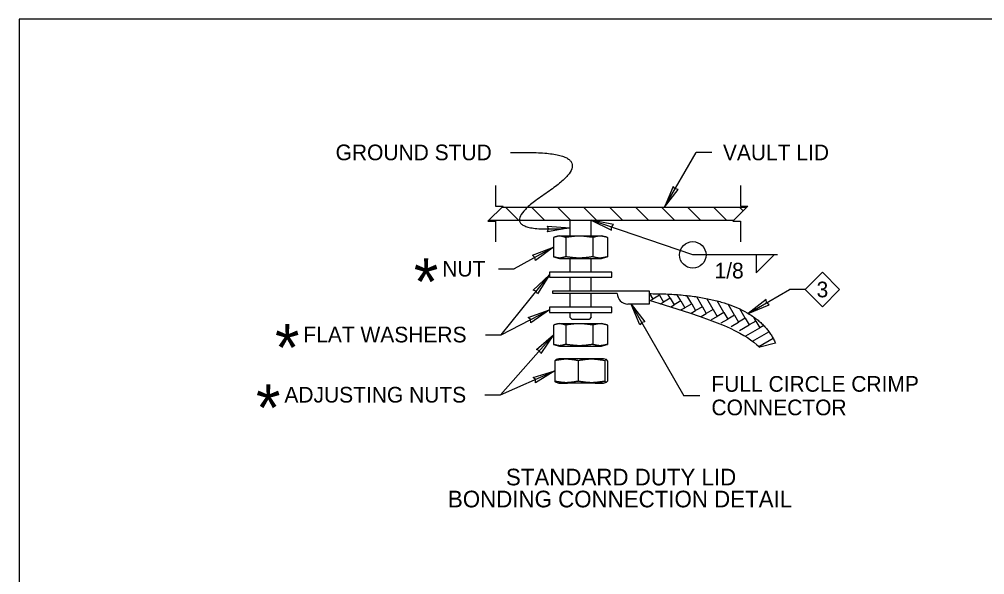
# Model space of a CAD drawing. Extents: x 99862 to 103151, y 100000 to 105076.
# Drawn here: x 99862 to 100847, y 104508 to 105076 of the extents above; entities that cross this region are included whole.
import ezdxf

# ---------------------------------------------------------------- set-up
doc = ezdxf.new("R2010")
doc.units = 0
for name, color, linetype in [('Level 1', 7, 'Continuous'), ('Level 10', 7, 'Continuous'), ('Level 11', 7, 'Continuous'), ('Level 13', 7, 'Continuous'), ('Level 15', 7, 'Continuous'), ('Level 20', 7, 'Continuous')]:
    doc.layers.add(name, color=color, linetype=linetype)

msp = doc.modelspace()

# ---------------------------------------------------------------- linework, layer by layer
at = {"layer": 'Level 1'}
for p, q in [((100354.24, 104883.61), (100604.11, 104883.61)), ((100358.14, 104883.61), (100371.32, 104870.43)), ((100384.66, 104883.61), (100397.84, 104870.43)), ((100411.17, 104883.61), (100424.35, 104870.43)), ((100437.69, 104883.61), (100450.87, 104870.43)), ((100464.21, 104883.61), (100477.39, 104870.43)), ((100490.72, 104883.61), (100503.9, 104870.43)), ((100517.24, 104883.61), (100530.42, 104870.43)), ((100543.76, 104883.61), (100556.93, 104870.43)), ((100570.27, 104883.61), (100583.45, 104870.43)), ((100596.79, 104883.61), (100600.45, 104879.95)), ((100341.06, 104870.43), (100590.93, 104870.43))]:
    msp.add_line(p, q, dxfattribs=at)
msp.add_lwpolyline([(99862, 102999.5), (103151, 102999.5), (103151, 105075.5), (99862, 105075.5)], close=True, dxfattribs=at)
at = {"layer": 'Level 10'}
for p, q in [((100423.63, 104870.43), (100423.63, 104854.53)), ((100445.5, 104854.53), (100445.5, 104870.43)), ((100413.14, 104854.53), (100407.73, 104853.02)), ((100413.14, 104854.53), (100455.99, 104854.53)), ((100461.4, 104853.02), (100455.99, 104854.53)), ((100407.75, 104853.03), (100406.97, 104852.8)), ((100406.97, 104852.8), (100406.97, 104833.11)), ((100419.42, 104852.8), (100419.42, 104833.11)), ((100447.01, 104852.8), (100447.01, 104833.11)), ((100461.38, 104853.03), (100462.16, 104852.8)), ((100462.16, 104852.8), (100462.16, 104833.11)), ((100406.97, 104833.09), (100413.14, 104831.38)), ((100413.14, 104831.38), (100455.99, 104831.38)), ((100423.63, 104831.38), (100423.63, 104817.43)), ((100445.5, 104817.43), (100445.5, 104831.38)), ((100455.99, 104831.38), (100461.4, 104832.88)), ((100461.38, 104832.88), (100462.16, 104833.11)), ((100423.63, 104812.16), (100423.63, 104798.34)), ((100445.5, 104798.34), (100445.5, 104812.16)), ((100423.63, 104795.71), (100423.63, 104781.57)), ((100445.5, 104781.57), (100445.5, 104795.71)), ((100423.63, 104776.3), (100423.63, 104771.38)), ((100445.5, 104771.38), (100445.5, 104776.3)), ((100425.88, 104769.13), (100423.63, 104771.38)), ((100443.25, 104769.13), (100425.88, 104769.13)), ((100445.5, 104771.38), (100443.25, 104769.13)), ((100407.75, 104763.57), (100406.97, 104763.34)), ((100406.97, 104763.34), (100406.97, 104743.65)), ((100413.14, 104765.07), (100407.73, 104763.57)), ((100413.14, 104765.07), (100455.99, 104765.07)), ((100419.42, 104763.34), (100419.42, 104743.65)), ((100447.01, 104763.34), (100447.01, 104743.65)), ((100461.4, 104763.57), (100455.99, 104765.07)), ((100461.38, 104763.57), (100462.16, 104763.34)), ((100462.16, 104763.34), (100462.16, 104743.65)), ((100406.97, 104743.64), (100413.14, 104741.92)), ((100413.14, 104741.92), (100455.99, 104741.92)), ((100455.99, 104741.92), (100461.4, 104743.43)), ((100461.38, 104743.42), (100462.16, 104743.65)), ((100408.37, 104727), (100409.6, 104728.06)), ((100408.37, 104727), (100408.37, 104706)), ((100412.41, 104728.85), (100409.56, 104728.05)), ((100432.27, 104727), (100432.27, 104706)), ((100460.97, 104728.06), (100458.12, 104728.85)), ((100459.17, 104727), (100459.17, 104706)), ((100462.16, 104727), (100460.93, 104728.07)), ((100462.16, 104727), (100462.16, 104706)), ((100408.37, 104706), (100409.6, 104704.93)), ((100409.56, 104704.94), (100412.41, 104704.15)), ((100458.12, 104704.15), (100460.97, 104704.95)), ((100462.16, 104706), (100460.93, 104704.94))]:
    msp.add_line(p, q, dxfattribs=at)
for centre, major_axis, start_param, end_param in [((100435.26, 104728.85), (22.85, 0), 0.625296, 3.141532), ((100435.26, 104728.85), (-14.06, 0), 0, 0.013106), ((100435.26, 104728.85), (22.85, 0), 0.00006, 0.625296), ((100435.27, 104704.15), (22.85, 0), 3.141653, 4.049582), ((100435.27, 104704.15), (22.85, 0), 0.625296, 3.141653), ((100435.27, 104704.15), (-14.06, 0), 0, 0.013106), ((100435.27, 104704.15), (-14.06, 0), 3.141593, 6.283185), ((100435.27, 104704.15), (22.85, 0), 5.37533, 6.283125), ((100435.27, 104704.15), (22.85, 0), 6.283125, 6.908482)]:
    msp.add_ellipse(centre, major_axis=major_axis, ratio=0.000017, start_param=start_param, end_param=end_param, dxfattribs=at)
for points in [[(100447.01, 104852.8), (100437.82, 104854.21), (100428.62, 104854.18), (100419.42, 104852.8)], [(100462.16, 104852.8), (100457.14, 104854.11), (100452.03, 104854.26), (100447.01, 104852.8)], [(100419.42, 104852.8), (100415.53, 104854.03), (100411.64, 104854.27), (100407.75, 104853.03)], [(100419.42, 104833.11), (100415.53, 104831.87), (100411.64, 104831.64), (100407.75, 104832.88)], [(100447.01, 104833.11), (100437.82, 104831.69), (100428.62, 104831.72), (100419.42, 104833.11)], [(100462.16, 104833.11), (100457.14, 104831.79), (100452.03, 104831.64), (100447.01, 104833.11)], [(100419.42, 104763.34), (100415.53, 104764.58), (100411.64, 104764.81), (100407.75, 104763.57)], [(100447.01, 104763.34), (100437.82, 104764.76), (100428.62, 104764.72), (100419.42, 104763.34)], [(100462.16, 104763.34), (100457.14, 104764.65), (100452.03, 104764.8), (100447.01, 104763.34)], [(100419.42, 104743.65), (100415.53, 104742.41), (100411.64, 104742.18), (100407.75, 104743.42)], [(100447.01, 104743.65), (100437.82, 104742.23), (100428.62, 104742.27), (100419.42, 104743.65)], [(100462.16, 104743.65), (100457.14, 104742.34), (100452.03, 104742.19), (100447.01, 104743.65)], [(100432.27, 104727), (100424.35, 104728.4), (100416.29, 104728.56), (100408.37, 104727)], [(100459.17, 104727), (100450.2, 104728.51), (100441.24, 104728.48), (100432.27, 104727)], [(100460.93, 104728.07), (100460.34, 104728.3), (100459.75, 104727.65), (100459.17, 104727)], [(100432.27, 104706), (100424.35, 104704.6), (100416.29, 104704.44), (100408.37, 104706)], [(100459.17, 104706), (100450.2, 104704.49), (100441.24, 104704.52), (100432.27, 104706)], [(100460.93, 104704.94), (100460.34, 104704.71), (100459.76, 104705.35), (100459.17, 104706)]]:
    msp.add_open_spline(points, degree=2, dxfattribs=at)
at = {"layer": 'Level 11'}
for p, q in [((100504.96, 104795.42), (100508.19, 104789.82)), ((100515.12, 104793.82), (100514.26, 104795.3)), ((100505.58, 104788.31), (100508.19, 104789.82)), ((100515.12, 104793.82), (100508.19, 104789.82)), ((100515.12, 104793.82), (100519.12, 104786.89)), ((100516.07, 104785.13), (100519.12, 104786.89)), ((100526.05, 104790.89), (100519.12, 104786.89)), ((100526.05, 104790.89), (100523.68, 104794.98)), ((100526.05, 104790.89), (100530.05, 104783.97)), ((100536.97, 104787.96), (100530.05, 104783.96)), ((100536.97, 104787.96), (100533.27, 104794.38)), ((100536.97, 104787.96), (100540.98, 104781.04)), ((100547.9, 104785.04), (100543.03, 104793.48)), ((100558.83, 104782.11), (100553.01, 104792.2)), ((100569.76, 104779.18), (100563.27, 104790.43)), ((100580.69, 104776.25), (100573.91, 104787.99)), ((100526.55, 104781.95), (100530.05, 104783.97)), ((100536.99, 104778.73), (100540.98, 104781.04)), ((100547.9, 104785.04), (100540.97, 104781.04)), ((100547.39, 104775.5), (100551.9, 104778.11)), ((100547.9, 104785.04), (100551.9, 104778.11)), ((100558.83, 104782.11), (100551.9, 104778.11)), ((100558.83, 104782.11), (100558.83, 104782.11)), ((100558.83, 104782.11), (100562.83, 104775.18)), ((100569.76, 104779.18), (100562.83, 104775.18)), ((100569.76, 104779.18), (100573.76, 104772.25)), ((100580.69, 104776.25), (100573.76, 104772.25)), ((100580.69, 104776.25), (100584.69, 104769.32)), ((100591.61, 104773.32), (100585.08, 104784.64)), ((100602.54, 104770.4), (100597.13, 104779.77)), ((100557.74, 104772.24), (100562.83, 104775.18)), ((100568, 104768.93), (100573.76, 104772.25)), ((100578.14, 104765.55), (100584.69, 104769.32)), ((100591.61, 104773.32), (100584.69, 104769.32)), ((100588.06, 104762.03), (100595.62, 104766.4)), ((100591.61, 104773.32), (100595.62, 104766.4)), ((100602.54, 104770.4), (100595.61, 104766.4)), ((100602.54, 104770.4), (100606.54, 104763.47)), ((100613.47, 104767.47), (100606.54, 104763.47)), ((100613.47, 104767.47), (100610.98, 104771.78)), ((100613.47, 104767.47), (100617.47, 104760.54)), ((100596.74, 104757.81), (100606.54, 104763.47)), ((100603.22, 104752.31), (100617.47, 104760.54)), ((100609.86, 104746.91), (100626.65, 104756.6)), ((100621.43, 104762.82), (100617.47, 104760.54)), ((100616.55, 104741.53), (100630.95, 104749.85)), ((100633.33, 104745.02), (100617.52, 104740.75))]:
    msp.add_line(p, q, dxfattribs=at)
for points, degree in [([(100504.38, 104795.43), (100611.24, 104795.43), (100633.33, 104745.02)], 2), ([(100504.38, 104788.68), (100591.83, 104762.34), (100599.86, 104754.87), (100617.52, 104740.75)], 3)]:
    msp.add_open_spline(points, degree=degree, dxfattribs=at)
at = {"layer": 'Level 13'}
for p, q in [((100406.12, 104795.71), (100406.12, 104798.34)), ((100406.12, 104798.34), (100415.52, 104798.34)), ((100415.52, 104795.71), (100406.12, 104795.71)), ((100415.52, 104798.34), (100452.22, 104798.34)), ((100452.22, 104795.71), (100415.52, 104795.71)), ((100452.22, 104798.34), (100458.25, 104798.34)), ((100458.25, 104795.71), (100452.22, 104795.71)), ((100458.25, 104798.34), (100470.04, 104798.34)), ((100471.92, 104795.71), (100458.25, 104795.71)), ((100470.04, 104798.34), (100504.38, 104798.34)), ((100504.38, 104798.34), (100504.38, 104784.77)), ((100504.38, 104784.77), (100482.86, 104784.77))]:
    msp.add_line(p, q, dxfattribs=at)
for points in [[(100402.7, 104817.43), (100402.7, 104812.16), (100466.43, 104812.16), (100466.43, 104817.43)], [(100402.7, 104781.57), (100402.7, 104776.3), (100466.43, 104776.3), (100466.43, 104781.57)]]:
    msp.add_lwpolyline(points, close=True, dxfattribs=at)
msp.add_arc((100482.86, 104795.71), 10.94, 180, 270, dxfattribs=at)
at = {"layer": 'Level 15'}
for p, q in [((100363.11, 104939.6), (100379.11, 104939.6)), ((100520.07, 104883.61), (100552.4, 104939.6)), ((100568.4, 104939.6), (100552.4, 104939.6)), ((100549.01, 104834.95), (100445.5, 104870.43)), ((100406.97, 104842.95), (100366.96, 104820.89)), ((100635.62, 104834.95), (100549.01, 104834.95)), ((100632.21, 104834.95), (100613.8, 104816.54)), ((100613.8, 104834.95), (100613.8, 104816.54)), ((100350.96, 104820.89), (100366.96, 104820.89)), ((100353.55, 104753.38), (100402.7, 104814.79)), ((100605.54, 104775.32), (100647.7, 104799.66)), ((100663.7, 104799.66), (100647.7, 104799.66)), ((100353.55, 104753.38), (100402.7, 104778.93)), ((100486.07, 104784.77), (100540.06, 104691.26)), ((100337.55, 104753.38), (100353.55, 104753.38)), ((100353.01, 104691.98), (100406.97, 104753.5)), ((100353.01, 104691.98), (100408.37, 104716.5)), ((100337.01, 104691.98), (100353.01, 104691.98)), ((100556.06, 104691.26), (100540.06, 104691.26))]:
    msp.add_line(p, q, dxfattribs=at)
for points in [[(100347.72, 104905.88), (100347.72, 104884.84), (100355.46, 104884.84), (100339.98, 104869.35), (100347.72, 104869.35), (100347.72, 104848.31)], [(100597.59, 104905.88), (100597.59, 104884.84), (100605.34, 104884.84), (100589.85, 104869.35), (100597.59, 104869.35), (100597.59, 104848.31)]]:
    msp.add_lwpolyline(points, dxfattribs=at)
for points in [[(100520.07, 104883.61), (100534.07, 104901.88), (100530.96, 104902.46), (100528.9, 104904.87)], [(100423.63, 104862.48), (100400.97, 104858.43), (100401.88, 104861.46), (100400.69, 104864.39)], [(100445.5, 104870.43), (100466.13, 104860.2), (100466.1, 104863.37), (100468.06, 104865.85)], [(100406.97, 104842.95), (100388.42, 104829.32), (100387.9, 104832.44), (100385.54, 104834.54)], [(100402.7, 104814.79), (100390.77, 104795.1), (100389.1, 104797.79), (100386.11, 104798.83)], [(100605.54, 104775.32), (100626.8, 104784.15), (100624.4, 104786.21), (100623.82, 104789.32)], [(100402.7, 104778.93), (100383.83, 104765.75), (100383.39, 104768.89), (100381.07, 104771.05)], [(100486.07, 104784.77), (100500.07, 104766.49), (100496.96, 104765.91), (100494.9, 104763.5)], [(100406.97, 104753.5), (100394.16, 104734.36), (100392.61, 104737.13), (100389.67, 104738.3)], [(100408.37, 104716.5), (100388.71, 104704.52), (100388.46, 104707.68), (100386.29, 104709.98)]]:
    msp.add_lwpolyline(points, close=True, dxfattribs=at)
msp.add_circle((100549.01, 104834.95), 13.54, dxfattribs=at)
msp.add_open_spline([(100379.11, 104939.6), (100462.14, 104939.6), (100335.22, 104855.37), (100423.63, 104862.48)], degree=2, dxfattribs=at)
at = {"layer": 'Level 20'}
msp.add_lwpolyline([(100681.25, 104817.22), (100698.81, 104799.66), (100681.25, 104782.11), (100663.7, 104799.66)], close=True, dxfattribs=at)

# ---------------------------------------------------------------- texts
for s, height, p in [('GROUND STUD', 16, (100184.67, 104931.6)), ('VAULT LID', 16, (100579.8, 104931.6)), ('*', 48, (100264.45, 104783.62)), ('NUT', 16, (100293.46, 104812.9)), ('1/8', 16, (100571.25, 104810.95)), ('3', 16, (100675.35, 104791.67)), ('*', 48, (100122.8, 104716.37)), ('FLAT WASHERS', 16, (100151.81, 104745.64)), ('*', 48, (100103.42, 104654.97)), ('ADJUSTING NUTS', 16, (100132.43, 104684.24)), ('STANDARD DUTY LID', 17, (100358.43, 104599.7)), ('BONDING CONNECTION DETAIL', 17, (100299.25, 104577.25))]:
    msp.add_text(s, height=height, dxfattribs=at).set_placement(p)
for s, p in [('FULL CIRCLE CRIMP ', (100568.06, 104695.27)), ('CONNECTOR', (100568.06, 104671.27))]:
    msp.add_text(s, height=16, rotation=360, dxfattribs=at).set_placement(p)

doc.saveas('drawing.dxf')
